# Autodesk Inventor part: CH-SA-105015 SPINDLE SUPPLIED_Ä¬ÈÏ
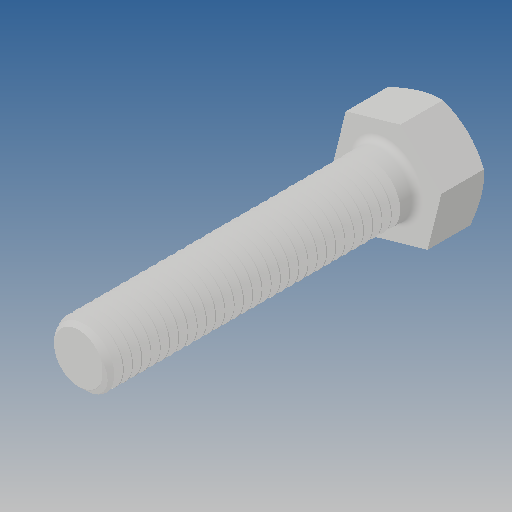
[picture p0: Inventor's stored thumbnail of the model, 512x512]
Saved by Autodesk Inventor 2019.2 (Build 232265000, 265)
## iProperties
Created: 2010-06
Part Number: CH-SA-105015 SPINDLE SUPPLIED_Ä¬ÈÏ
Material: Ogólny
Document SubType Name: Modeling
Designer: CADENGINEERING4
Density: 1 g/cm^3
Appearance: Domyślna
Author: CADENGINEERING4
Revision Number: ÈÎºÎ
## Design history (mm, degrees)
feature "NONE"
node "Bryła1"
